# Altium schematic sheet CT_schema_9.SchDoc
size 274 x 160 mm
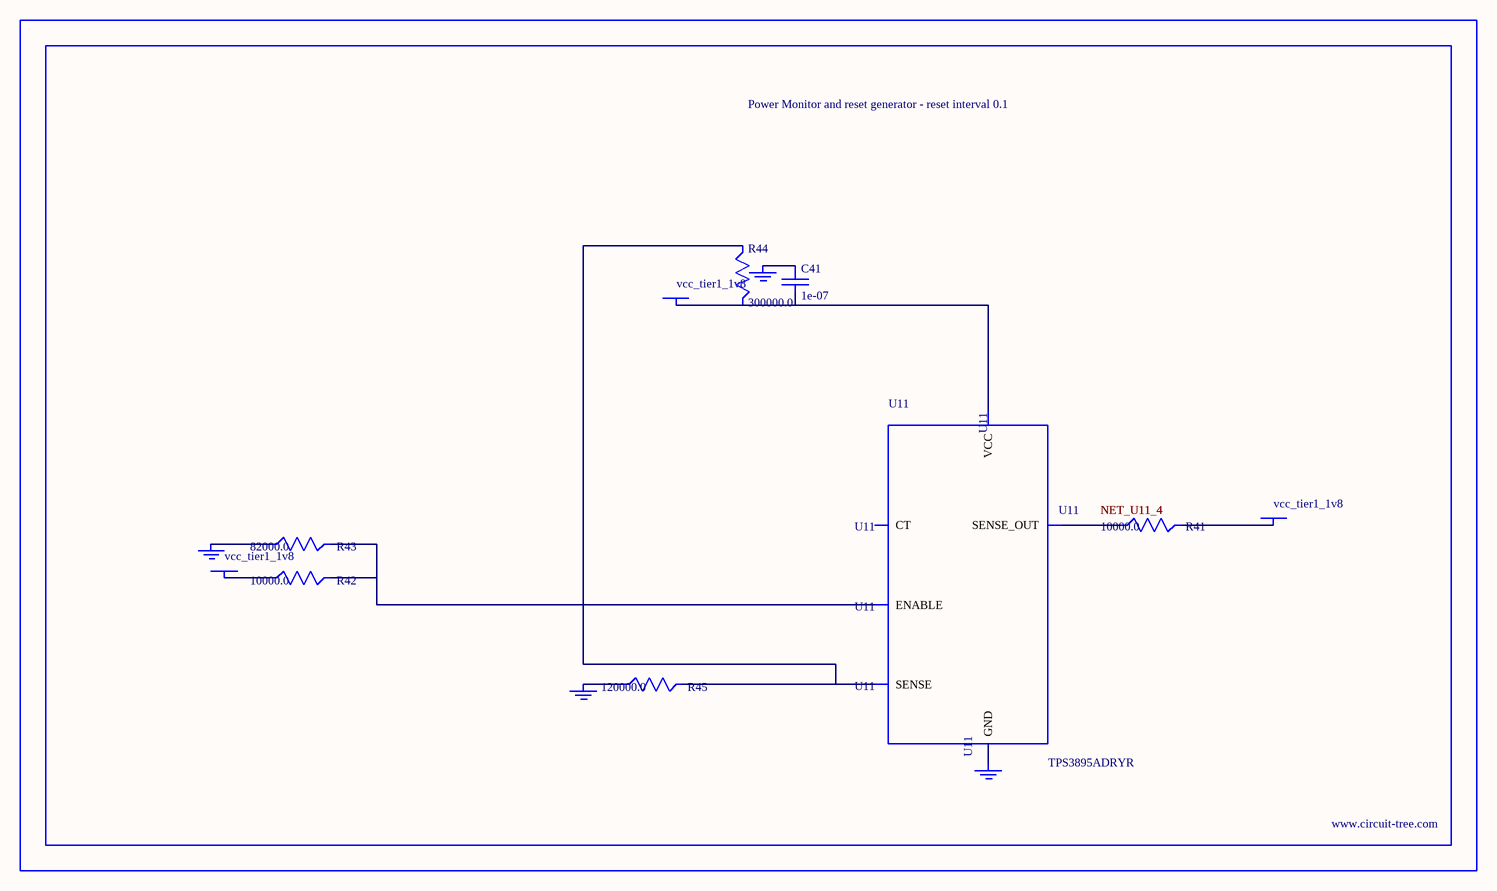
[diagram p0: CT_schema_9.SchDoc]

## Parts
BORDER8  (no value)
C41  1e-07  [C0402]
GND_INSTANCE_8_0  (no value)
GND_INSTANCE_8_1  (no value)
GND_INSTANCE_8_2  (no value)
GND_INSTANCE_8_3  (no value)
POWER_INSTANCE_8_0  vcc_tier1_1v8
POWER_INSTANCE_8_1  vcc_tier1_1v8
POWER_INSTANCE_8_2  vcc_tier1_1v8
R41  10000.0  [R0603]
R42  10000.0  [R0603]
R43  82000.0  [R0603]
R44  300000.0  [R0603]
R45  120000.0  [R0603]
U11  TPS3895ADRYR  [SON-6]

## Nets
NetC41_1: C41.1 GND_INSTANCE_8_2.0(GND)
NetC41_2: C41.2 POWER_INSTANCE_8_2.0(PWR) R44.2 U11.6(VCC)
NetGND_INSTANCE_8_0_0: GND_INSTANCE_8_0.0(GND) R43.1
NetGND_INSTANCE_8_1_0: GND_INSTANCE_8_1.0(GND) R45.1
NetGND_INSTANCE_8_3_0: GND_INSTANCE_8_3.0(GND) U11.2(GND)
NetPOWER_INSTANCE_8_0_0: POWER_INSTANCE_8_0.0(PWR) R42.1
NetPOWER_INSTANCE_8_1_0: POWER_INSTANCE_8_1.0(PWR) R41.2
NetR41_1: R41.1 U11.4(SENSE_OUT)
NetR42_2: R42.2 R43.2 U11.1(ENABLE)
NetR44_1: R44.1 R45.2 U11.3(SENSE)

Not connected (* = marked no-connect by the designer): U11 5(CT)

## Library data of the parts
BORDER8 = BORDER_PAGE8
C41 = C0402C104K3RACTU
GND_INSTANCE_8_0-GND_INSTANCE_8_3 = GND
POWER_INSTANCE_8_0-POWER_INSTANCE_8_2 = PWR
R41 R42 = RC0603JR-0710KL
R43 = RC0603JR-0782KL
R44 = RC0603JR-07300KL
R45 = RC0603JR-07120KL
